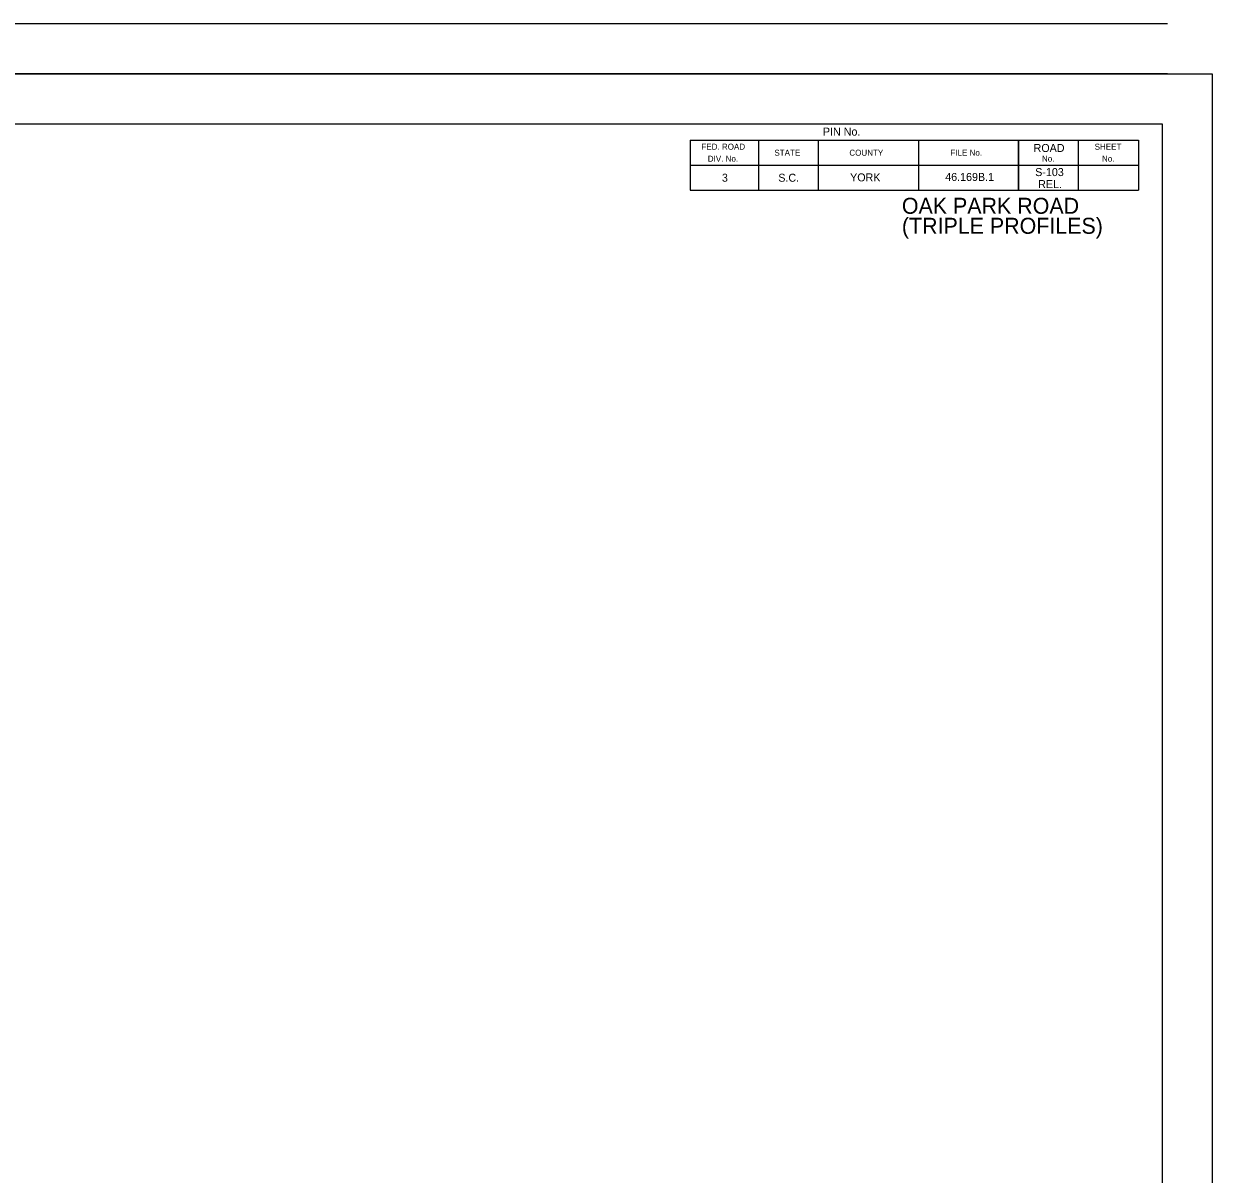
# Model space of a CAD drawing. Extents: x 49817 to 52197, y 49938 to 51088.
# Drawn here: x 51019 to 51613, y 50513 to 51088 of the extents above; entities that cross this region are included whole.
import ezdxf

# ---------------------------------------------------------------- set-up
doc = ezdxf.new("R2010")
doc.units = 0
for name, color, linetype in [('RD_SHT_Bndy', 7, 'Continuous'), ('RD_SHT_Iplotshp', 7, 'Continuous'), ('RD_SHT_TX', 7, 'Continuous')]:
    doc.layers.add(name, color=color, linetype=linetype)

msp = doc.modelspace()

# ---------------------------------------------------------------- linework, layer by layer
at = {"layer": 'RD_SHT_Bndy'}
for p, q in [((51590.65, 51087.5), (49830.65, 51087.5)), ((51590.65, 51062.5), (49830.65, 51062.5)), ((51352.15, 51029.3), (51352.15, 51004.3)), ((51352.15, 51029.3), (51516.15, 51029.3)), ((51386.15, 51029.3), (51386.15, 51004.3)), ((51416.15, 51004.3), (51416.15, 51029.3)), ((51466.15, 51029.3), (51466.15, 51004.3)), ((51516.15, 51004.3), (51516.15, 51029.3)), ((51516.15, 51029.3), (51516.15, 51004.3)), ((51516.15, 51029.3), (51576.15, 51029.3)), ((51546.15, 51004.3), (51546.15, 51029.3)), ((51576.15, 51029.3), (51576.15, 51004.3)), ((51352.15, 51016.8), (51516.15, 51016.8)), ((51516.15, 51016.8), (51576.15, 51016.8)), ((51352.15, 51004.3), (51516.15, 51004.3)), ((51516.15, 51004.3), (51576.15, 51004.3))]:
    msp.add_line(p, q, dxfattribs=at)
msp.add_lwpolyline([(49913.05, 51037.5), (51588, 51037.5), (51588, 49987.5), (49913.05, 49987.5)], close=True, dxfattribs=at)
at = {"layer": 'RD_SHT_Iplotshp'}
msp.add_lwpolyline([(49817.1, 51062.5), (51613, 51062.5), (51613, 49962.5), (49817.1, 49962.5)], close=True, dxfattribs=at)

# ---------------------------------------------------------------- texts
at = {"layer": 'RD_SHT_TX'}
for s, height, p in [('PIN No.           ', 4, (51418.42, 51031.6)), ('FED. ROAD', 3, (51357.7, 51024.55)), ('STATE', 3, (51394.17, 51021.55)), ('COUNTY', 3, (51431.64, 51021.55)), ('FILE No.', 3, (51482.15, 51021.55)), ('ROAD', 4, (51523.73, 51023.42)), ('SHEET', 3, (51554.23, 51024.55)), ('DIV. No.', 3, (51360.89, 51018.55)), ('No.', 3, (51527.91, 51018.55)), ('No.', 3, (51557.91, 51018.55)), ('3', 4, (51367.95, 51008.55)), ('S.C.', 4, (51396.13, 51008.55)), ('YORK', 4, (51432.02, 51008.72)), ('46.169B.1', 4, (51479.56, 51008.94)), ('S-103', 4, (51524.53, 51011.37)), (' REL.', 4, (51524.53, 51005.37)), ('OAK PARK ROAD', 8, (51457.89, 50992.53)), ('(TRIPLE PROFILES)', 8, (51457.89, 50982.53))]:
    msp.add_text(s, height=height, dxfattribs=at).set_placement(p)

doc.saveas('drawing.dxf')
